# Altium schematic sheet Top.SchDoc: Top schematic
size A3; DocumentNumber: MB1144; Revision: B-02; SheetNumber: 1; SheetTotal: 25; PageSetup: Record=PageOptions|CenterHorizontal=True|CenterVertical=True|PrintScale=1.01|XCorrection=1.00|YCorrection=1.00|PrintKind=1|BorderSize=5000000|LeftOffset=0|BottomOffset=0|Orientation=2|PaperLength=1000|PaperWidth=1000|Scale=100|PaperSource=264|PrintQuality=600|MediaType=1|DitherType=10|PaperKind=A3|PrintScaleMode=1; Project: STM32L476G-EVAL
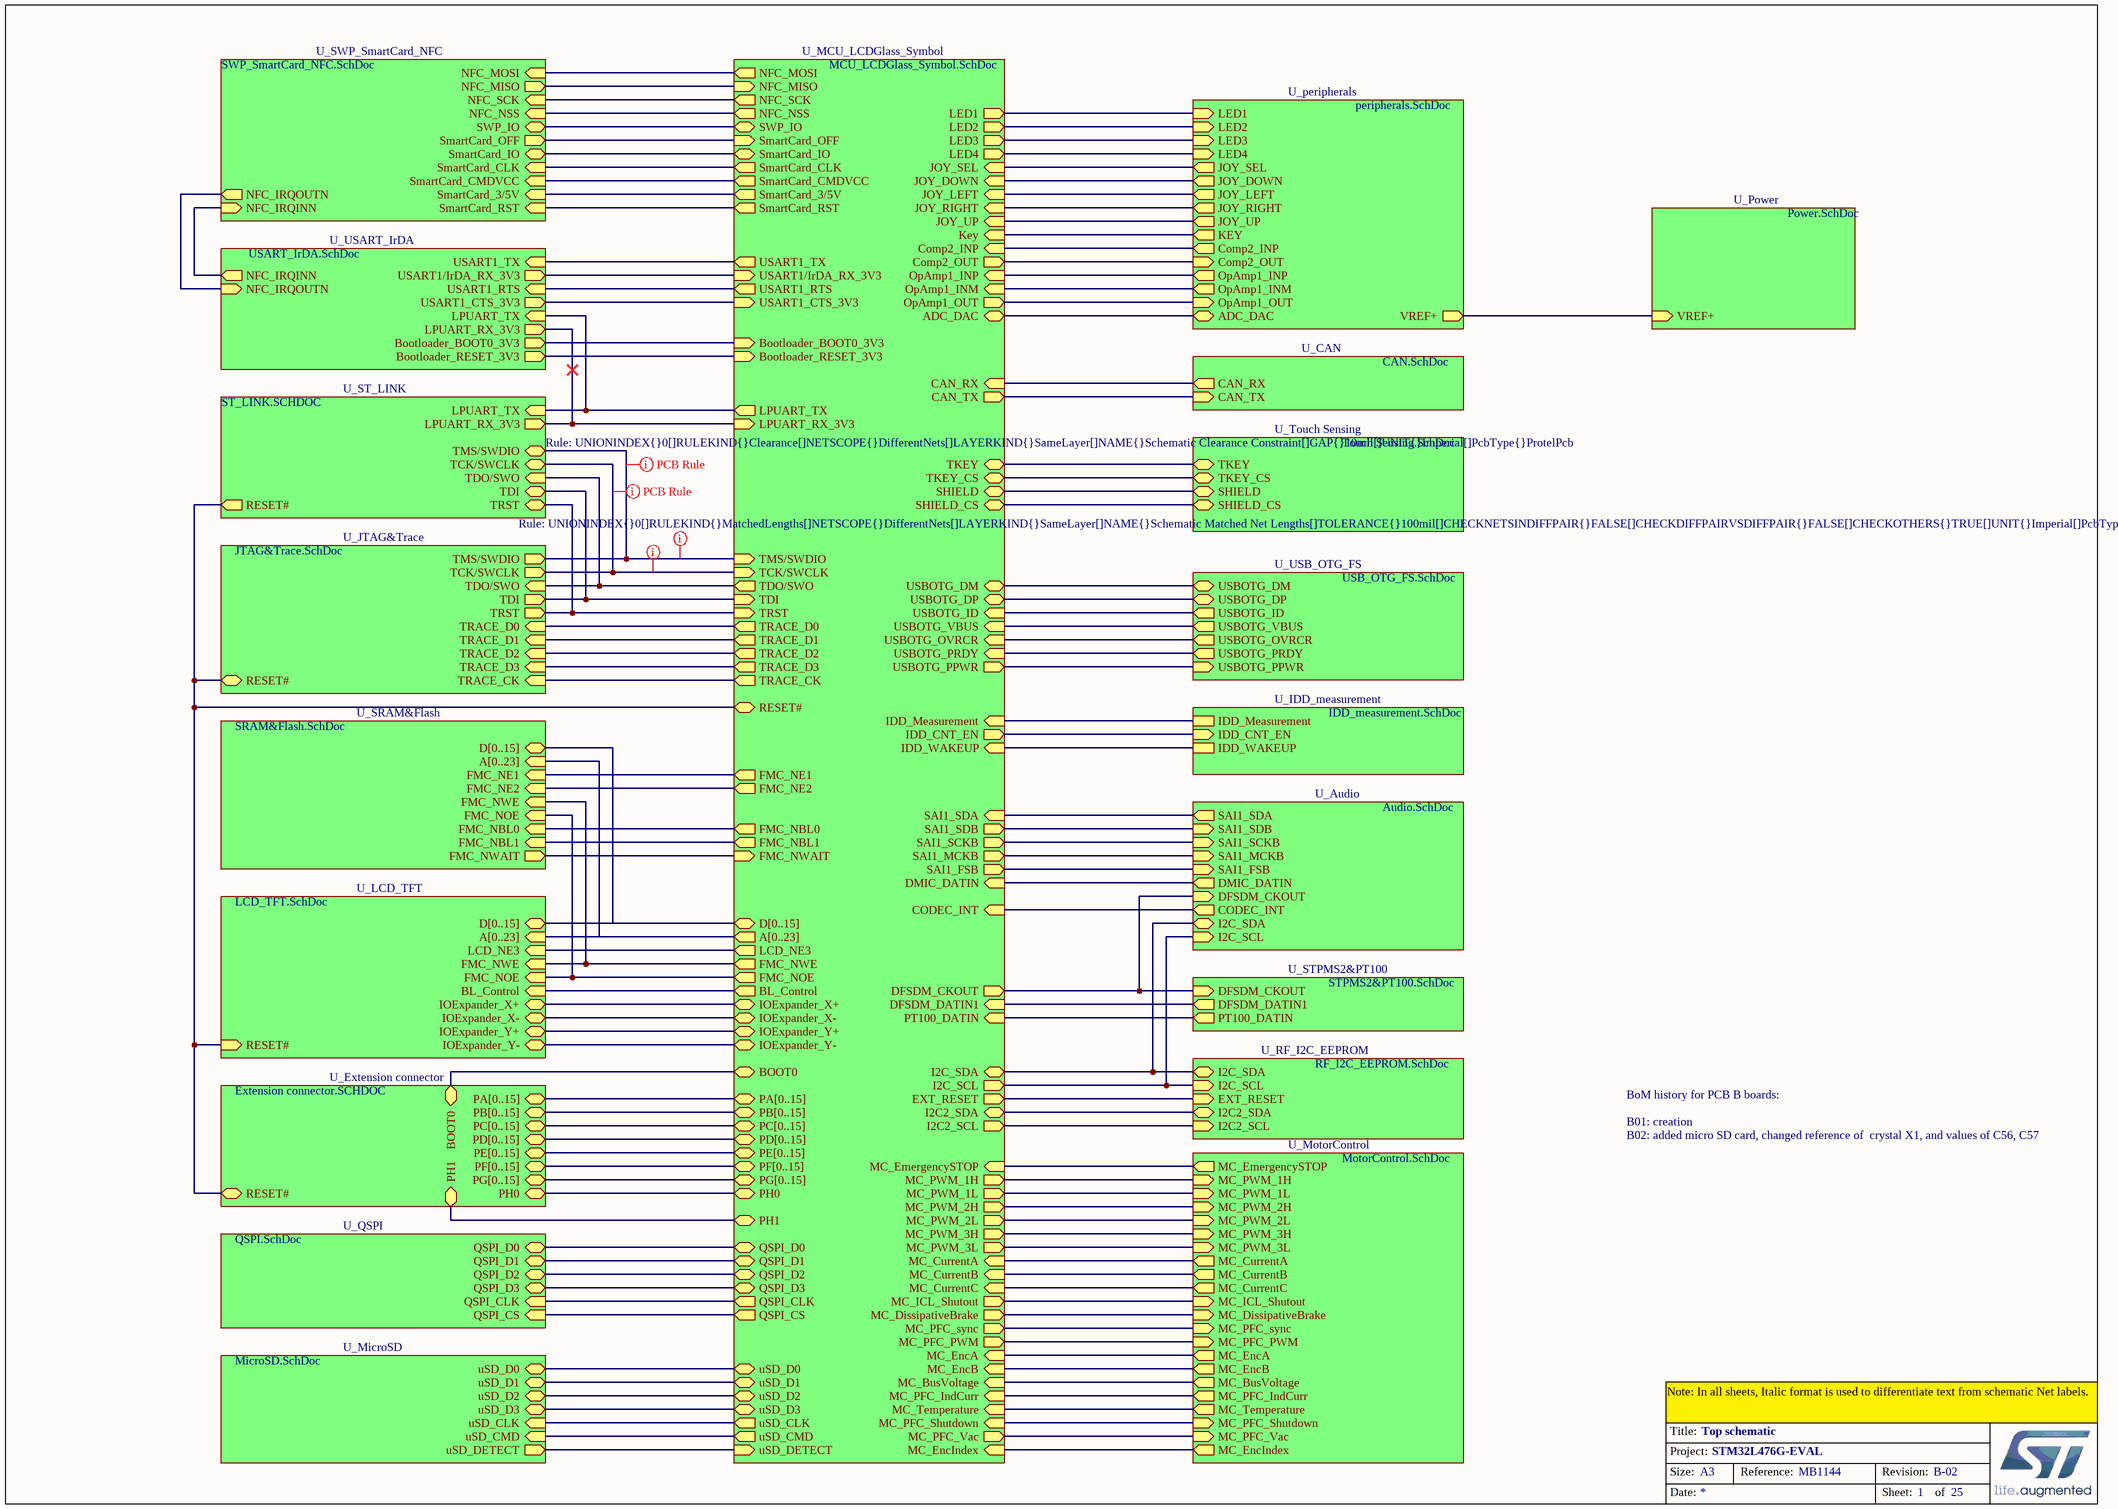
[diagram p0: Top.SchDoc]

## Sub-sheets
U_Audio = Audio.SchDoc: SAI1_SCKB (in), SAI1_FSB (in), SAI1_SDB (in), CODEC_INT (out), I2C_SCL (in), SAI1_MCKB (in), I2C_SDA (bidir), DMIC_DATIN (out), DFSDM_CKOUT (in), SAI1_SDA (out)
U_CAN = CAN.SchDoc: CAN_TX (in), CAN_RX (out)
U_Extension connector = Extension connector.SCHDOC: PA[0..15] (bidir), PB[0..15] (bidir), PC[0..15] (bidir), PD[0..15] (bidir), PE[0..15] (bidir), RESET# (bidir), PF[0..15] (bidir), PG[0..15] (bidir), PH1, PH0, BOOT0
U_IDD_measurement = IDD_measurement.SchDoc: IDD_Measurement, IDD_CNT_EN (in), IDD_WAKEUP
U_JTAG&Trace = JTAG&Trace.SchDoc: TDI (out), RESET# (bidir), TRACE_D3 (in), TRACE_D2 (in), TRACE_D1 (in), TRACE_D0 (in), TRACE_CK (in), TRST (out), TMS/SWDIO (out), TCK/SWCLK (out), TDO/SWO (in)
U_LCD_TFT = LCD_TFT.SchDoc: RESET# (in), FMC_NWE (in), LCD_NE3 (in), FMC_NOE (in), D[0..15] (bidir), A[0..23] (in), IOExpander_Y+ (bidir), IOExpander_Y- (bidir), IOExpander_X+ (bidir), IOExpander_X- (bidir), BL_Control (in)
U_MCU_LCDGlass_Symbol = MCU_LCDGlass_Symbol.SchDoc: FMC_NWAIT (in), FMC_NOE (out), FMC_NWE (out), FMC_NE1 (out), FMC_NE2 (out), LCD_NE3 (out), LED1 (out), LED2 (out), LPUART_TX (out), USART1_TX (out), USART1_RTS (out), TMS/SWDIO (in), TCK/SWCLK (in), TDI (in), TRST (in), Key (in), DFSDM_DATIN1 (in), IDD_Measurement (in), CODEC_INT (in), USBOTG_PRDY (in), USBOTG_OVRCR (in), DMIC_DATIN (in), PT100_DATIN (in), USBOTG_VBUS (in), USBOTG_ID (in), IDD_WAKEUP (in), OpAmp1_INM (in), Comp2_INP (in), TDO/SWO (out), TRACE_D1 (out), TRACE_D2 (out), TRACE_D3 (out), IDD_CNT_EN (out), USBOTG_PPWR (out), TRACE_CK (out), TRACE_D0 (out), SmartCard_CLK (out), OpAmp1_OUT (out), ADC_DAC (bidir), USBOTG_DP (bidir), USBOTG_DM (bidir), SmartCard_IO (bidir), QSPI_D0 (bidir), QSPI_D1 (bidir), QSPI_D2 (bidir), QSPI_D3 (bidir), uSD_D0 (bidir), uSD_D1 (bidir), uSD_D2 (bidir), uSD_D3 (bidir), MC_DissipativeBrake (out), MC_PFC_sync (out), MC_PWM_1H (out), MC_PWM_1L (out), MC_PWM_2H (out), MC_PWM_2L (out), MC_PWM_3H (out), MC_PWM_3L (out), MC_ICL_Shutout (out), MC_PFC_PWM (out), MC_PFC_Vac (out), QSPI_CLK (out), QSPI_CS (out), FMC_NBL0 (out), FMC_NBL1 (out), CAN_TX (out), MC_EncA (in), MC_EncB (in), MC_EncIndex (in), MC_CurrentB (in), MC_CurrentC (in), MC_Temperature (in), MC_PFC_Shutdown (in), CAN_RX (in), uSD_DETECT (in), uSD_CMD (out), uSD_CLK (out), SWP_IO (bidir), IOExpander_X+ (bidir), IOExpander_X- (bidir), IOExpander_Y+ (bidir), IOExpander_Y- (bidir), JOY_SEL (in), JOY_DOWN (in), JOY_LEFT (in), JOY_RIGHT (in), JOY_UP (in), SmartCard_OFF (in), LED4 (out), LED3 (out), SmartCard_RST (out), SmartCard_CMDVCC (out), SmartCard_3/5V (out), D[0..15] (bidir), A[0..23] (out), PA[0..15] (bidir), PB[0..15] (bidir), PC[0..15] (bidir), PD[0..15] (bidir), PE[0..15] (bidir), PF[0..15] (bidir), PG[0..15] (bidir), MC_CurrentA (in), MC_EmergencySTOP (in), MC_BusVoltage (in), MC_PFC_IndCurr (in), RESET# (bidir), DFSDM_CKOUT (out), I2C_SCL (out), I2C_SDA (bidir), PH1, PH0, SHIELD, SAI1_MCKB (out), SAI1_SCKB (out), SAI1_FSB (out), SAI1_SDB (out), SAI1_SDA (in), OpAmp1_INP (in), Comp2_OUT (out), TKEY, TKEY_CS, SHIELD_CS, Bootloader_RESET_3V3 (in), Bootloader_BOOT0_3V3 (in), LPUART_RX_3V3 (in), USART1_CTS_3V3 (in), USART1/IrDA_RX_3V3 (in), BL_Control (out), EXT_RESET (out), BOOT0, NFC_NSS (out), NFC_MOSI (out), NFC_SCK (out), NFC_MISO (in), I2C2_SDA (bidir), I2C2_SCL (out)
U_MicroSD = MicroSD.SchDoc: uSD_CLK (in), uSD_CMD (in), uSD_D0 (bidir), uSD_D1 (bidir), uSD_D2 (bidir), uSD_D3 (bidir), uSD_DETECT (out)
U_MotorControl = MotorControl.SchDoc: MC_EmergencySTOP (out), MC_CurrentA (out), MC_CurrentB (out), MC_CurrentC (out), MC_PFC_sync (in), MC_PWM_3L (in), MC_PWM_2H (in), MC_PWM_2L (in), MC_PWM_1H (in), MC_PWM_1L (in), MC_PWM_3H (in), MC_ICL_Shutout (in), MC_DissipativeBrake (in), MC_PFC_PWM (in), MC_EncA (out), MC_EncB (out), MC_BusVoltage (out), MC_EncIndex (out), MC_PFC_IndCurr (out), MC_Temperature (out), MC_PFC_Shutdown (in), MC_PFC_Vac (in)
U_peripherals = peripherals.SchDoc: ADC_DAC (bidir), LED4 (in), LED3 (in), LED1 (in), LED2 (in), JOY_SEL (out), JOY_DOWN (out), JOY_LEFT (out), JOY_RIGHT (out), JOY_UP (out), KEY (out), VREF+ (out), Comp2_INP (out), OpAmp1_OUT (in), OpAmp1_INM (out), OpAmp1_INP (out), Comp2_OUT (in)
U_Power = Power.SchDoc: VREF+ (in)
U_QSPI = QSPI.SchDoc: QSPI_D0 (bidir), QSPI_D3 (bidir), QSPI_D2 (bidir), QSPI_D1 (bidir), QSPI_CLK (in), QSPI_CS (in)
U_RF_I2C_EEPROM = RF_I2C_EEPROM.SchDoc: I2C_SCL (in), I2C_SDA (bidir), EXT_RESET (in), I2C2_SDA (bidir), I2C2_SCL (in)
U_SRAM&Flash = SRAM&Flash.SchDoc: FMC_NWE (in), FMC_NOE (in), FMC_NWAIT (out), FMC_NBL0 (in), FMC_NBL1 (in), D[0..15] (bidir), A[0..23] (in), FMC_NE1 (in), FMC_NE2 (in)
U_ST_LINK = ST_LINK.SCHDOC: TDO/SWO (in), RESET# (out), TDI, TRST, TMS/SWDIO, TCK/SWCLK, LPUART_RX_3V3 (out), LPUART_TX (in)
U_STPMS2&PT100 = STPMS2&PT100.SchDoc: DFSDM_CKOUT (in), DFSDM_DATIN1 (out), PT100_DATIN (out)
U_SWP_SmartCard_NFC = SWP_SmartCard_NFC.SchDoc: SWP_IO (bidir), SmartCard_3/5V (in), SmartCard_IO (bidir), SmartCard_RST (in), SmartCard_CLK (in), SmartCard_OFF (out), SmartCard_CMDVCC (in), NFC_IRQINN (in), NFC_IRQOUTN (out), NFC_NSS (in), NFC_MOSI (in), NFC_MISO (out), NFC_SCK (in)
U_Touch Sensing = Touch Sensing.SchDoc: SHIELD, SHIELD_CS, TKEY_CS, TKEY
U_USART_IrDA = USART_IrDA.SchDoc: USART1/IrDA_RX_3V3 (out), Bootloader_BOOT0_3V3 (out), Bootloader_RESET_3V3 (out), USART1_CTS_3V3 (out), USART1_TX (in), USART1_RTS (in), LPUART_RX_3V3 (out), LPUART_TX (in), NFC_IRQINN (out), NFC_IRQOUTN (in)
U_USB_OTG_FS = USB_OTG_FS.SchDoc: USBOTG_VBUS (out), USBOTG_PRDY (out), USBOTG_DM (bidir), USBOTG_DP (bidir), USBOTG_OVRCR (out), USBOTG_PPWR (in), USBOTG_ID (out)

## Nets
(unnamed): sheet U_MCU_LCDGlass_Symbol/FMC_NWAIT, sheet U_SRAM&Flash/FMC_NWAIT
(unnamed): sheet U_MCU_LCDGlass_Symbol/FMC_NOE, sheet U_SRAM&Flash/FMC_NOE, sheet U_LCD_TFT/FMC_NOE  [a separate net that carries the same name]
(unnamed): sheet U_MCU_LCDGlass_Symbol/FMC_NWE, sheet U_SRAM&Flash/FMC_NWE, sheet U_LCD_TFT/FMC_NWE  [a separate net that carries the same name]
(unnamed): sheet U_MCU_LCDGlass_Symbol/FMC_NE1, sheet U_SRAM&Flash/FMC_NE1  [a separate net that carries the same name]
(unnamed): sheet U_MCU_LCDGlass_Symbol/FMC_NE2, sheet U_SRAM&Flash/FMC_NE2  [a separate net that carries the same name]
(unnamed): sheet U_MCU_LCDGlass_Symbol/LCD_NE3, sheet U_LCD_TFT/LCD_NE3  [a separate net that carries the same name]
(unnamed): sheet U_MCU_LCDGlass_Symbol/LED1, sheet U_peripherals/LED1  [a separate net that carries the same name]
(unnamed): sheet U_MCU_LCDGlass_Symbol/LED2, sheet U_peripherals/LED2  [a separate net that carries the same name]
(unnamed): sheet U_MCU_LCDGlass_Symbol/LPUART_TX, sheet U_ST_LINK/LPUART_TX, sheet U_USART_IrDA/LPUART_TX  [a separate net that carries the same name]
(unnamed): sheet U_MCU_LCDGlass_Symbol/USART1_TX, sheet U_USART_IrDA/USART1_TX  [a separate net that carries the same name]
(unnamed): sheet U_MCU_LCDGlass_Symbol/USART1_RTS, sheet U_USART_IrDA/USART1_RTS  [a separate net that carries the same name]
(unnamed): sheet U_MCU_LCDGlass_Symbol/TMS/SWDIO, sheet U_JTAG&Trace/TMS/SWDIO, sheet U_ST_LINK/TMS/SWDIO  [a separate net that carries the same name]
(unnamed): sheet U_MCU_LCDGlass_Symbol/TCK/SWCLK, sheet U_JTAG&Trace/TCK/SWCLK, sheet U_ST_LINK/TCK/SWCLK  [a separate net that carries the same name]
(unnamed): sheet U_MCU_LCDGlass_Symbol/TDI, sheet U_JTAG&Trace/TDI, sheet U_ST_LINK/TDI  [a separate net that carries the same name]
(unnamed): sheet U_MCU_LCDGlass_Symbol/TRST, sheet U_JTAG&Trace/TRST, sheet U_ST_LINK/TRST  [a separate net that carries the same name]
(unnamed): sheet U_MCU_LCDGlass_Symbol/Key, sheet U_peripherals/KEY  [a separate net that carries the same name]
(unnamed): sheet U_MCU_LCDGlass_Symbol/DFSDM_DATIN1, sheet U_STPMS2&PT100/DFSDM_DATIN1  [a separate net that carries the same name]
(unnamed): sheet U_MCU_LCDGlass_Symbol/IDD_Measurement, sheet U_IDD_measurement/IDD_Measurement  [a separate net that carries the same name]
(unnamed): sheet U_MCU_LCDGlass_Symbol/CODEC_INT, sheet U_Audio/CODEC_INT  [a separate net that carries the same name]
(unnamed): sheet U_MCU_LCDGlass_Symbol/USBOTG_PRDY, sheet U_USB_OTG_FS/USBOTG_PRDY  [a separate net that carries the same name]
(unnamed): sheet U_MCU_LCDGlass_Symbol/USBOTG_OVRCR, sheet U_USB_OTG_FS/USBOTG_OVRCR  [a separate net that carries the same name]
(unnamed): sheet U_MCU_LCDGlass_Symbol/DMIC_DATIN, sheet U_Audio/DMIC_DATIN  [a separate net that carries the same name]
(unnamed): sheet U_MCU_LCDGlass_Symbol/PT100_DATIN, sheet U_STPMS2&PT100/PT100_DATIN  [a separate net that carries the same name]
(unnamed): sheet U_MCU_LCDGlass_Symbol/USBOTG_VBUS, sheet U_USB_OTG_FS/USBOTG_VBUS  [a separate net that carries the same name]
(unnamed): sheet U_MCU_LCDGlass_Symbol/USBOTG_ID, sheet U_USB_OTG_FS/USBOTG_ID  [a separate net that carries the same name]
(unnamed): sheet U_MCU_LCDGlass_Symbol/IDD_WAKEUP, sheet U_IDD_measurement/IDD_WAKEUP  [a separate net that carries the same name]
(unnamed): sheet U_MCU_LCDGlass_Symbol/OpAmp1_INM, sheet U_peripherals/OpAmp1_INM  [a separate net that carries the same name]
(unnamed): sheet U_MCU_LCDGlass_Symbol/Comp2_INP, sheet U_peripherals/Comp2_INP  [a separate net that carries the same name]
(unnamed): sheet U_MCU_LCDGlass_Symbol/TDO/SWO, sheet U_JTAG&Trace/TDO/SWO, sheet U_ST_LINK/TDO/SWO  [a separate net that carries the same name]
(unnamed): sheet U_MCU_LCDGlass_Symbol/TRACE_D1, sheet U_JTAG&Trace/TRACE_D1  [a separate net that carries the same name]
(unnamed): sheet U_MCU_LCDGlass_Symbol/TRACE_D2, sheet U_JTAG&Trace/TRACE_D2  [a separate net that carries the same name]
(unnamed): sheet U_MCU_LCDGlass_Symbol/TRACE_D3, sheet U_JTAG&Trace/TRACE_D3  [a separate net that carries the same name]
(unnamed): sheet U_MCU_LCDGlass_Symbol/IDD_CNT_EN, sheet U_IDD_measurement/IDD_CNT_EN  [a separate net that carries the same name]
(unnamed): sheet U_MCU_LCDGlass_Symbol/USBOTG_PPWR, sheet U_USB_OTG_FS/USBOTG_PPWR  [a separate net that carries the same name]
(unnamed): sheet U_MCU_LCDGlass_Symbol/TRACE_CK, sheet U_JTAG&Trace/TRACE_CK  [a separate net that carries the same name]
(unnamed): sheet U_MCU_LCDGlass_Symbol/TRACE_D0, sheet U_JTAG&Trace/TRACE_D0  [a separate net that carries the same name]
(unnamed): sheet U_MCU_LCDGlass_Symbol/SmartCard_CLK, sheet U_SWP_SmartCard_NFC/SmartCard_CLK  [a separate net that carries the same name]
(unnamed): sheet U_MCU_LCDGlass_Symbol/OpAmp1_OUT, sheet U_peripherals/OpAmp1_OUT  [a separate net that carries the same name]
(unnamed): sheet U_MCU_LCDGlass_Symbol/ADC_DAC, sheet U_peripherals/ADC_DAC  [a separate net that carries the same name]
(unnamed): sheet U_MCU_LCDGlass_Symbol/USBOTG_DP, sheet U_USB_OTG_FS/USBOTG_DP  [a separate net that carries the same name]
(unnamed): sheet U_MCU_LCDGlass_Symbol/USBOTG_DM, sheet U_USB_OTG_FS/USBOTG_DM  [a separate net that carries the same name]
(unnamed): sheet U_MCU_LCDGlass_Symbol/SmartCard_IO, sheet U_SWP_SmartCard_NFC/SmartCard_IO  [a separate net that carries the same name]
(unnamed): sheet U_MCU_LCDGlass_Symbol/QSPI_D0, sheet U_QSPI/QSPI_D0  [a separate net that carries the same name]
(unnamed): sheet U_MCU_LCDGlass_Symbol/QSPI_D1, sheet U_QSPI/QSPI_D1  [a separate net that carries the same name]
(unnamed): sheet U_MCU_LCDGlass_Symbol/QSPI_D2, sheet U_QSPI/QSPI_D2  [a separate net that carries the same name]
(unnamed): sheet U_MCU_LCDGlass_Symbol/QSPI_D3, sheet U_QSPI/QSPI_D3  [a separate net that carries the same name]
(unnamed): sheet U_MCU_LCDGlass_Symbol/uSD_D0, sheet U_MicroSD/uSD_D0  [a separate net that carries the same name]
(unnamed): sheet U_MCU_LCDGlass_Symbol/uSD_D1, sheet U_MicroSD/uSD_D1  [a separate net that carries the same name]
(unnamed): sheet U_MCU_LCDGlass_Symbol/uSD_D2, sheet U_MicroSD/uSD_D2  [a separate net that carries the same name]
(unnamed): sheet U_MCU_LCDGlass_Symbol/uSD_D3, sheet U_MicroSD/uSD_D3  [a separate net that carries the same name]
(unnamed): sheet U_MCU_LCDGlass_Symbol/MC_DissipativeBrake, sheet U_MotorControl/MC_DissipativeBrake  [a separate net that carries the same name]
(unnamed): sheet U_MCU_LCDGlass_Symbol/MC_PFC_sync, sheet U_MotorControl/MC_PFC_sync  [a separate net that carries the same name]
(unnamed): sheet U_MCU_LCDGlass_Symbol/MC_PWM_1H, sheet U_MotorControl/MC_PWM_1H  [a separate net that carries the same name]
(unnamed): sheet U_MCU_LCDGlass_Symbol/MC_PWM_1L, sheet U_MotorControl/MC_PWM_1L  [a separate net that carries the same name]
(unnamed): sheet U_MCU_LCDGlass_Symbol/MC_PWM_2H, sheet U_MotorControl/MC_PWM_2H  [a separate net that carries the same name]
(unnamed): sheet U_MCU_LCDGlass_Symbol/MC_PWM_2L, sheet U_MotorControl/MC_PWM_2L  [a separate net that carries the same name]
(unnamed): sheet U_MCU_LCDGlass_Symbol/MC_PWM_3H, sheet U_MotorControl/MC_PWM_3H  [a separate net that carries the same name]
(unnamed): sheet U_MCU_LCDGlass_Symbol/MC_PWM_3L, sheet U_MotorControl/MC_PWM_3L  [a separate net that carries the same name]
(unnamed): sheet U_MCU_LCDGlass_Symbol/MC_ICL_Shutout, sheet U_MotorControl/MC_ICL_Shutout  [a separate net that carries the same name]
(unnamed): sheet U_MCU_LCDGlass_Symbol/MC_PFC_PWM, sheet U_MotorControl/MC_PFC_PWM  [a separate net that carries the same name]
(unnamed): sheet U_MCU_LCDGlass_Symbol/MC_PFC_Vac, sheet U_MotorControl/MC_PFC_Vac  [a separate net that carries the same name]
(unnamed): sheet U_MCU_LCDGlass_Symbol/QSPI_CLK, sheet U_QSPI/QSPI_CLK  [a separate net that carries the same name]
(unnamed): sheet U_MCU_LCDGlass_Symbol/QSPI_CS, sheet U_QSPI/QSPI_CS  [a separate net that carries the same name]
(unnamed): sheet U_MCU_LCDGlass_Symbol/FMC_NBL0, sheet U_SRAM&Flash/FMC_NBL0  [a separate net that carries the same name]
(unnamed): sheet U_MCU_LCDGlass_Symbol/FMC_NBL1, sheet U_SRAM&Flash/FMC_NBL1  [a separate net that carries the same name]
(unnamed): sheet U_MCU_LCDGlass_Symbol/CAN_TX, sheet U_CAN/CAN_TX  [a separate net that carries the same name]
(unnamed): sheet U_MCU_LCDGlass_Symbol/MC_EncA, sheet U_MotorControl/MC_EncA  [a separate net that carries the same name]
(unnamed): sheet U_MCU_LCDGlass_Symbol/MC_EncB, sheet U_MotorControl/MC_EncB  [a separate net that carries the same name]
(unnamed): sheet U_MCU_LCDGlass_Symbol/MC_EncIndex, sheet U_MotorControl/MC_EncIndex  [a separate net that carries the same name]
(unnamed): sheet U_MCU_LCDGlass_Symbol/MC_CurrentB, sheet U_MotorControl/MC_CurrentB  [a separate net that carries the same name]
(unnamed): sheet U_MCU_LCDGlass_Symbol/MC_CurrentC, sheet U_MotorControl/MC_CurrentC  [a separate net that carries the same name]
(unnamed): sheet U_MCU_LCDGlass_Symbol/MC_Temperature, sheet U_MotorControl/MC_Temperature  [a separate net that carries the same name]
(unnamed): sheet U_MCU_LCDGlass_Symbol/MC_PFC_Shutdown, sheet U_MotorControl/MC_PFC_Shutdown  [a separate net that carries the same name]
(unnamed): sheet U_MCU_LCDGlass_Symbol/CAN_RX, sheet U_CAN/CAN_RX  [a separate net that carries the same name]
(unnamed): sheet U_MCU_LCDGlass_Symbol/uSD_DETECT, sheet U_MicroSD/uSD_DETECT  [a separate net that carries the same name]
(unnamed): sheet U_MCU_LCDGlass_Symbol/uSD_CMD, sheet U_MicroSD/uSD_CMD  [a separate net that carries the same name]
(unnamed): sheet U_MCU_LCDGlass_Symbol/uSD_CLK, sheet U_MicroSD/uSD_CLK  [a separate net that carries the same name]
(unnamed): sheet U_MCU_LCDGlass_Symbol/SWP_IO, sheet U_SWP_SmartCard_NFC/SWP_IO  [a separate net that carries the same name]
(unnamed): sheet U_MCU_LCDGlass_Symbol/IOExpander_X+, sheet U_LCD_TFT/IOExpander_X+  [a separate net that carries the same name]
(unnamed): sheet U_MCU_LCDGlass_Symbol/IOExpander_X-, sheet U_LCD_TFT/IOExpander_X-  [a separate net that carries the same name]
(unnamed): sheet U_MCU_LCDGlass_Symbol/IOExpander_Y+, sheet U_LCD_TFT/IOExpander_Y+  [a separate net that carries the same name]
(unnamed): sheet U_MCU_LCDGlass_Symbol/IOExpander_Y-, sheet U_LCD_TFT/IOExpander_Y-  [a separate net that carries the same name]
(unnamed): sheet U_MCU_LCDGlass_Symbol/JOY_SEL, sheet U_peripherals/JOY_SEL  [a separate net that carries the same name]
(unnamed): sheet U_MCU_LCDGlass_Symbol/JOY_DOWN, sheet U_peripherals/JOY_DOWN  [a separate net that carries the same name]
(unnamed): sheet U_MCU_LCDGlass_Symbol/JOY_LEFT, sheet U_peripherals/JOY_LEFT  [a separate net that carries the same name]
(unnamed): sheet U_MCU_LCDGlass_Symbol/JOY_RIGHT, sheet U_peripherals/JOY_RIGHT  [a separate net that carries the same name]
(unnamed): sheet U_MCU_LCDGlass_Symbol/JOY_UP, sheet U_peripherals/JOY_UP  [a separate net that carries the same name]
(unnamed): sheet U_MCU_LCDGlass_Symbol/SmartCard_OFF, sheet U_SWP_SmartCard_NFC/SmartCard_OFF  [a separate net that carries the same name]
(unnamed): sheet U_MCU_LCDGlass_Symbol/LED4, sheet U_peripherals/LED4  [a separate net that carries the same name]
(unnamed): sheet U_MCU_LCDGlass_Symbol/LED3, sheet U_peripherals/LED3  [a separate net that carries the same name]
(unnamed): sheet U_MCU_LCDGlass_Symbol/SmartCard_RST, sheet U_SWP_SmartCard_NFC/SmartCard_RST  [a separate net that carries the same name]
(unnamed): sheet U_MCU_LCDGlass_Symbol/SmartCard_CMDVCC, sheet U_SWP_SmartCard_NFC/SmartCard_CMDVCC  [a separate net that carries the same name]
(unnamed): sheet U_MCU_LCDGlass_Symbol/SmartCard_3/5V, sheet U_SWP_SmartCard_NFC/SmartCard_3/5V  [a separate net that carries the same name]
(unnamed): sheet U_MCU_LCDGlass_Symbol/MC_CurrentA, sheet U_MotorControl/MC_CurrentA  [a separate net that carries the same name]
(unnamed): sheet U_MCU_LCDGlass_Symbol/MC_EmergencySTOP, sheet U_MotorControl/MC_EmergencySTOP  [a separate net that carries the same name]
(unnamed): sheet U_MCU_LCDGlass_Symbol/MC_BusVoltage, sheet U_MotorControl/MC_BusVoltage  [a separate net that carries the same name]
(unnamed): sheet U_MCU_LCDGlass_Symbol/MC_PFC_IndCurr, sheet U_MotorControl/MC_PFC_IndCurr  [a separate net that carries the same name]
(unnamed): sheet U_MCU_LCDGlass_Symbol/RESET#, sheet U_Extension connector/RESET#, sheet U_JTAG&Trace/RESET#, sheet U_ST_LINK/RESET#, sheet U_LCD_TFT/RESET#  [a separate net that carries the same name]
(unnamed): sheet U_MCU_LCDGlass_Symbol/DFSDM_CKOUT, sheet U_STPMS2&PT100/DFSDM_CKOUT, sheet U_Audio/DFSDM_CKOUT  [a separate net that carries the same name]
(unnamed): sheet U_MCU_LCDGlass_Symbol/I2C_SCL, sheet U_Audio/I2C_SCL, sheet U_RF_I2C_EEPROM/I2C_SCL  [a separate net that carries the same name]
(unnamed): sheet U_MCU_LCDGlass_Symbol/I2C_SDA, sheet U_Audio/I2C_SDA, sheet U_RF_I2C_EEPROM/I2C_SDA  [a separate net that carries the same name]
(unnamed): sheet U_MCU_LCDGlass_Symbol/PH1, sheet U_Extension connector/PH1  [a separate net that carries the same name]
(unnamed): sheet U_MCU_LCDGlass_Symbol/PH0, sheet U_Extension connector/PH0  [a separate net that carries the same name]
(unnamed): sheet U_MCU_LCDGlass_Symbol/SHIELD, sheet U_Touch Sensing/SHIELD  [a separate net that carries the same name]
(unnamed): sheet U_MCU_LCDGlass_Symbol/SAI1_MCKB, sheet U_Audio/SAI1_MCKB  [a separate net that carries the same name]
(unnamed): sheet U_MCU_LCDGlass_Symbol/SAI1_SCKB, sheet U_Audio/SAI1_SCKB  [a separate net that carries the same name]
(unnamed): sheet U_MCU_LCDGlass_Symbol/SAI1_FSB, sheet U_Audio/SAI1_FSB  [a separate net that carries the same name]
(unnamed): sheet U_MCU_LCDGlass_Symbol/SAI1_SDB, sheet U_Audio/SAI1_SDB  [a separate net that carries the same name]
(unnamed): sheet U_MCU_LCDGlass_Symbol/SAI1_SDA, sheet U_Audio/SAI1_SDA  [a separate net that carries the same name]
(unnamed): sheet U_MCU_LCDGlass_Symbol/OpAmp1_INP, sheet U_peripherals/OpAmp1_INP  [a separate net that carries the same name]
(unnamed): sheet U_MCU_LCDGlass_Symbol/Comp2_OUT, sheet U_peripherals/Comp2_OUT  [a separate net that carries the same name]
(unnamed): sheet U_MCU_LCDGlass_Symbol/TKEY, sheet U_Touch Sensing/TKEY  [a separate net that carries the same name]
(unnamed): sheet U_MCU_LCDGlass_Symbol/TKEY_CS, sheet U_Touch Sensing/TKEY_CS  [a separate net that carries the same name]
(unnamed): sheet U_MCU_LCDGlass_Symbol/SHIELD_CS, sheet U_Touch Sensing/SHIELD_CS  [a separate net that carries the same name]
(unnamed): sheet U_MCU_LCDGlass_Symbol/Bootloader_RESET_3V3, sheet U_USART_IrDA/Bootloader_RESET_3V3  [a separate net that carries the same name]
(unnamed): sheet U_MCU_LCDGlass_Symbol/Bootloader_BOOT0_3V3, sheet U_USART_IrDA/Bootloader_BOOT0_3V3  [a separate net that carries the same name]
(unnamed): sheet U_MCU_LCDGlass_Symbol/LPUART_RX_3V3, sheet U_ST_LINK/LPUART_RX_3V3, sheet U_USART_IrDA/LPUART_RX_3V3  [a separate net that carries the same name]
(unnamed): sheet U_MCU_LCDGlass_Symbol/USART1_CTS_3V3, sheet U_USART_IrDA/USART1_CTS_3V3  [a separate net that carries the same name]
(unnamed): sheet U_MCU_LCDGlass_Symbol/USART1/IrDA_RX_3V3, sheet U_USART_IrDA/USART1/IrDA_RX_3V3  [a separate net that carries the same name]
(unnamed): sheet U_MCU_LCDGlass_Symbol/BL_Control, sheet U_LCD_TFT/BL_Control  [a separate net that carries the same name]
(unnamed): sheet U_MCU_LCDGlass_Symbol/EXT_RESET, sheet U_RF_I2C_EEPROM/EXT_RESET  [a separate net that carries the same name]
(unnamed): sheet U_MCU_LCDGlass_Symbol/BOOT0, sheet U_Extension connector/BOOT0  [a separate net that carries the same name]
(unnamed): sheet U_MCU_LCDGlass_Symbol/NFC_NSS, sheet U_SWP_SmartCard_NFC/NFC_NSS  [a separate net that carries the same name]
(unnamed): sheet U_MCU_LCDGlass_Symbol/NFC_MOSI, sheet U_SWP_SmartCard_NFC/NFC_MOSI  [a separate net that carries the same name]
(unnamed): sheet U_MCU_LCDGlass_Symbol/NFC_SCK, sheet U_SWP_SmartCard_NFC/NFC_SCK  [a separate net that carries the same name]
(unnamed): sheet U_MCU_LCDGlass_Symbol/NFC_MISO, sheet U_SWP_SmartCard_NFC/NFC_MISO  [a separate net that carries the same name]
(unnamed): sheet U_MCU_LCDGlass_Symbol/I2C2_SDA, sheet U_RF_I2C_EEPROM/I2C2_SDA  [a separate net that carries the same name]
(unnamed): sheet U_MCU_LCDGlass_Symbol/I2C2_SCL, sheet U_RF_I2C_EEPROM/I2C2_SCL  [a separate net that carries the same name]
(unnamed): sheet U_USART_IrDA/NFC_IRQINN, sheet U_SWP_SmartCard_NFC/NFC_IRQINN  [a separate net that carries the same name]
(unnamed): sheet U_USART_IrDA/NFC_IRQOUTN, sheet U_SWP_SmartCard_NFC/NFC_IRQOUTN  [a separate net that carries the same name]
(unnamed): sheet U_peripherals/VREF+, sheet U_Power/VREF+  [a separate net that carries the same name]

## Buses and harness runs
bus sheet U_Extension connector/PA[0..15] = sheet U_MCU_LCDGlass_Symbol/PA[0..15]
bus sheet U_Extension connector/PB[0..15] = sheet U_MCU_LCDGlass_Symbol/PB[0..15]
bus sheet U_Extension connector/PC[0..15] = sheet U_MCU_LCDGlass_Symbol/PC[0..15]
bus sheet U_Extension connector/PD[0..15] = sheet U_MCU_LCDGlass_Symbol/PD[0..15]
bus sheet U_Extension connector/PE[0..15] = sheet U_MCU_LCDGlass_Symbol/PE[0..15]
bus sheet U_Extension connector/PF[0..15] = sheet U_MCU_LCDGlass_Symbol/PF[0..15]
bus sheet U_Extension connector/PG[0..15] = sheet U_MCU_LCDGlass_Symbol/PG[0..15]
bus sheet U_LCD_TFT/A[0..23] = sheet U_MCU_LCDGlass_Symbol/A[0..23] = sheet U_SRAM&Flash/A[0..23]
bus sheet U_LCD_TFT/D[0..15] = sheet U_MCU_LCDGlass_Symbol/D[0..15] = sheet U_SRAM&Flash/D[0..15]

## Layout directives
rule Matched Net Lengths [Tolerance = 100mil]: (no net found under the mark)
rule Clearance Constraint [Clearance = 10mil]: (no net found under the mark)

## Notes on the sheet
- BoM history for PCB B boards:
  B01: creation
  B02: added micro SD card, changed reference of  crystal X1, and values of C56, C57
- Note: In all sheets, Italic format is used to differentiate text from schematic Net labels.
